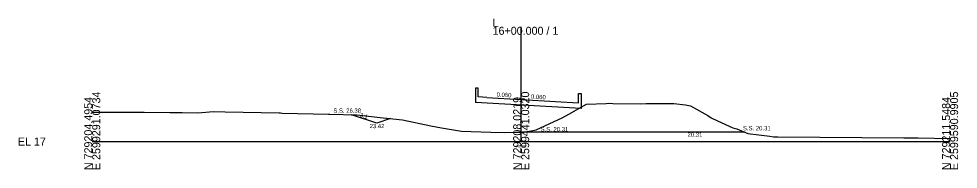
# Model space of a CAD drawing. Extents: x -26 to 3303, y -10 to 9555.
# Drawn here: x 974.3 to 1302.8, y 1990.3 to 2043 of the extents above; entities that cross this region are included whole.
import ezdxf

# ---------------------------------------------------------------- set-up
doc = ezdxf.new("R2010")
doc.units = 0
for name, color, linetype in [('Exist Cross Section Cell', 7, 'Continuous'), ('Exist XS Center Line Elevation Label', 7, 'Continuous'), ('Exist XS Ground Line', 7, 'Continuous'), ('Prop XS Bridge', 7, 'Continuous'), ('Prop XS Ditch Standard Text', 7, 'Continuous'), ('Prop XS Dump Level', 7, 'Continuous'), ('Prop XS Earthwork Shape', 7, 'Continuous'), ('Prop XS Finish Grade Earthwork', 7, 'Continuous'), ('Prop XS Finish Grade Pavement', 7, 'Continuous'), ('Prop XS SE Text', 7, 'Continuous'), ('Prop XS Side Slope Text', 7, 'Continuous'), ('Prop XS SS Elevation Text', 7, 'Continuous')]:
    doc.layers.add(name, color=color, linetype=linetype)

msp = doc.modelspace()

# ---------------------------------------------------------------- linework, layer by layer
at = {"layer": 'Exist Cross Section Cell'}
for p, q in [((1150, 2000), (1150, 2040.17)), ((1000, 2000), (1150, 2000)), ((1150, 2000), (1300, 2000))]:
    msp.add_line(p, q, dxfattribs=at)
at = {"layer": 'Exist XS Ground Line'}
msp.add_lwpolyline([(1000, 2010.31), (1011.87, 2010.23), (1013.45, 2010.23), (1014.92, 2010.24), (1018.2, 2010.23), (1027.08, 2010.2), (1031.44, 2010.13), (1036.75, 2010.01), (1038.34, 2010.2), (1042.36, 2010.51), (1046.48, 2010.43), (1065.36, 2010.01), (1065.83, 2009.99), (1066.45, 2009.97), (1082.64, 2009.61), (1083.07, 2009.6), (1092.56, 2009.32), (1101.71, 2008.32), (1108.52, 2007.57), (1118.4, 2005.54), (1122.11, 2004.84), (1129.14, 2003.6), (1139.36, 2003.24), (1144.2, 2003.13), (1148.11, 2003.28), (1150, 2003.3), (1151, 2003.32), (1155.29, 2004.13), (1163, 2007.69), (1164.38, 2008.27), (1166.62, 2009.58), (1172.89, 2013.09), (1179.68, 2013.33), (1180.89, 2013.39), (1182.09, 2013.35), (1191.75, 2013.25), (1193.75, 2013.26), (1203.38, 2013.27), (1207.51, 2012.85), (1209.21, 2012.52), (1215.29, 2009.16), (1216.44, 2008.35), (1218.69, 2007.27), (1224.07, 2004.85), (1225.41, 2004.39), (1229.29, 2002.81), (1237, 2001.89), (1238.3, 2001.66), (1239.19, 2001.65), (1239.8, 2001.66), (1283.81, 2001.24), (1288.87, 2001.27), (1300, 2001.09)], dxfattribs=at)
at = {"layer": 'Prop XS Bridge'}
for p, q in [((1134, 2018.65), (1134, 2015.65)), ((1135, 2018.65), (1134, 2018.65)), ((1135, 2015.65), (1135, 2018.65)), ((1134, 2015.65), (1134, 2013.65)), ((1138, 2015.47), (1135, 2015.65)), ((1138, 2015.47), (1150, 2014.75)), ((1150, 2014.75), (1162, 2014.03)), ((1162, 2014.03), (1170, 2013.55)), ((1170, 2013.55), (1170, 2016.85)), ((1170, 2016.85), (1171, 2016.85)), ((1171, 2016.85), (1171, 2013.85)), ((1171, 2011.56), (1134, 2013.65)), ((1171, 2013.85), (1171, 2011.56))]:
    msp.add_line(p, q, dxfattribs=at)
at = {"layer": 'Prop XS Dump Level'}
msp.add_line((1150, 2014.75), (1162, 2014.03), dxfattribs=at)
at = {"layer": 'Prop XS Earthwork Shape'}
for points in [[(1163, 2007.69), (1164.38, 2008.27), (1166.62, 2009.58), (1172.89, 2013.09), (1179.68, 2013.33), (1180.89, 2013.39), (1182.09, 2013.35), (1191.75, 2013.25), (1193.75, 2013.26), (1203.38, 2013.27), (1207.51, 2012.85), (1209.21, 2012.52), (1215.29, 2009.16), (1216.44, 2008.35), (1218.69, 2007.27), (1224.07, 2004.85), (1225.41, 2004.39), (1228.06, 2003.31), (1150.41, 2003.31), (1151, 2003.32), (1155.29, 2004.13)], [(1228.06, 2003.31), (1150.41, 2003.31), (1151, 2003.32), (1155.29, 2004.13), (1163, 2007.69), (1164.38, 2008.27), (1166.62, 2009.58), (1172.89, 2013.09), (1179.68, 2013.33), (1180.89, 2013.39), (1182.09, 2013.35), (1191.75, 2013.25), (1193.75, 2013.26), (1203.38, 2013.27), (1207.51, 2012.85), (1209.21, 2012.52), (1215.29, 2009.16), (1216.44, 2008.35), (1218.69, 2007.27), (1224.07, 2004.85), (1225.41, 2004.39)], [(1101.71, 2008.32), (1104.33, 2008.03), (1099.5, 2006.42), (1090.62, 2009.38), (1092.56, 2009.32)], [(1099.5, 2006.42), (1090.62, 2009.38), (1092.56, 2009.32), (1101.71, 2008.32), (1104.33, 2008.03)]]:
    msp.add_lwpolyline(points, close=True, dxfattribs=at)
at = {"layer": 'Prop XS Finish Grade Earthwork'}
for p, q in [((1099.5, 2006.42), (1090.62, 2009.38)), ((1104.33, 2008.03), (1099.5, 2006.42)), ((1228.06, 2003.31), (1150.41, 2003.31))]:
    msp.add_line(p, q, dxfattribs=at)
at = {"layer": 'Prop XS Finish Grade Pavement'}
msp.add_line((1138, 2015.47), (1150, 2014.75), dxfattribs=at)

# ---------------------------------------------------------------- texts
at = {"layer": 'Exist Cross Section Cell'}
for s, p in [('16+00.000 / 1', (1140, 2037.37)), ('L', (1140, 2040.17)), ('EL 17', (974, 1998.6))]:
    msp.add_text(s, height=2.8, dxfattribs=at).set_placement(p)
for s, p in [('E 2599291.0734', (1002.8, 1990)), ('E 2599441.0320', (1152.8, 1990)), ('E 2599590.9905', (1302.8, 1990)), ('N 729204.4954', (1000, 1990)), ('N 729208.0219', (1150, 1990)), ('N 729211.5484', (1300, 1990))]:
    msp.add_text(s, height=2.8, rotation=90, dxfattribs=at).set_placement(p)
at = {"layer": 'Exist XS Center Line Elevation Label'}
msp.add_text('20.30', height=1, dxfattribs=at).set_placement((1148.25, 1997.8))
at = {"layer": 'Prop XS Ditch Standard Text'}
msp.add_text('20.31', height=1.5, dxfattribs=at).set_placement((1208.18, 2001.68))
at = {"layer": 'Prop XS SE Text'}
for p in [(1141.38, 2015.76), (1153.38, 2015.04)]:
    msp.add_text('0.060', height=1.5, rotation=356.5664, dxfattribs=at).set_placement(p)
at = {"layer": 'Prop XS Side Slope Text'}
msp.add_text('3:1', height=1.5, rotation=341.0185, dxfattribs=at).set_placement((1093.39, 2008.73))
at = {"layer": 'Prop XS SS Elevation Text'}
for s, p in [('S.S. 26.38', (1084.33, 2010.07)), ('23.42', (1097, 2004.68)), ('S.S. 20.31', (1156.79, 2003.56)), ('S.S. 20.31', (1227.57, 2003.93))]:
    msp.add_text(s, height=1.5, dxfattribs=at).set_placement(p)

doc.saveas('drawing.dxf')
